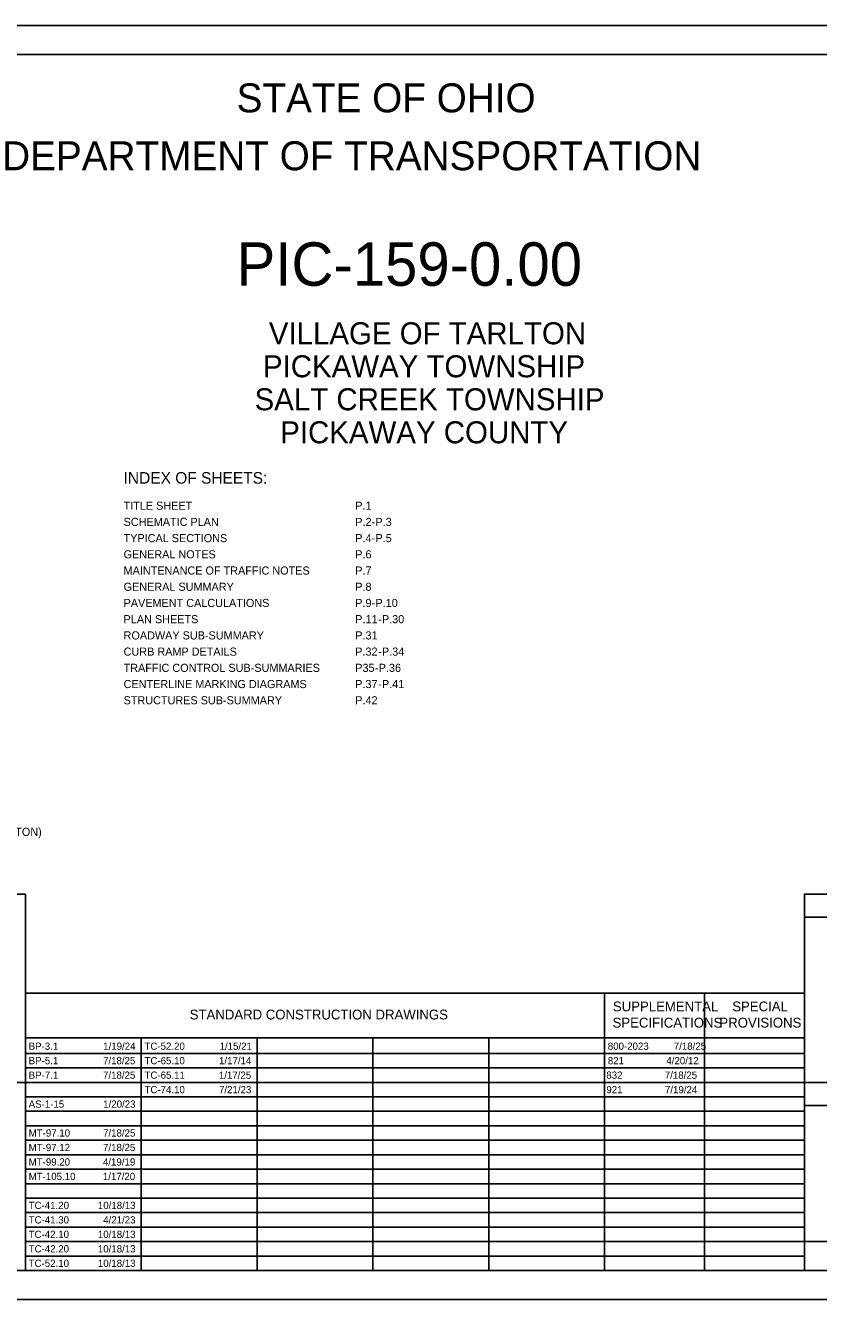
# Model space of a CAD drawing. Extents: x 0 to 42.5, y 0 to 22.
# Drawn here: x 10.15 to 23.84, y 0 to 22 of the extents above; entities that cross this region are included whole.
import ezdxf

# ---------------------------------------------------------------- set-up
doc = ezdxf.new("R2010")
doc.units = 0
for name, color, linetype in [('Default', 7, 'Continuous'), ('SH_Border', 7, 'Continuous'), ('SH_Cut_Line', 7, 'Continuous'), ('SH_Data', 7, 'Continuous'), ('SH_Text', 7, 'Continuous')]:
    doc.layers.add(name, color=color, linetype=linetype)

msp = doc.modelspace()

# ---------------------------------------------------------------- linework, layer by layer
at = {"layer": 'SH_Border'}
msp.add_lwpolyline([(1.5, 21.5), (33.5, 21.5), (33.5, 0.5), (1.5, 0.5)], close=True, dxfattribs=at)
at = {"layer": 'SH_Cut_Line'}
msp.add_lwpolyline([(0, 0), (34, 0), (34, 22), (0, 22)], close=True, dxfattribs=at)
at = {"layer": 'SH_Data'}
for p, q in [((23.6, 6.6), (26.4, 6.6)), ((10.15, 5.292), (23.6, 5.292)), ((10.15, 0.5), (10.15, 5.292)), ((20.15, 0.5), (20.15, 5.292)), ((21.875, 0.5), (21.875, 5.292)), ((23.6, 0.5), (23.6, 5.292)), ((10.15, 4.521), (23.6, 4.521)), ((12.15, 0.5), (12.15, 4.521)), ((14.15, 0.5), (14.15, 4.521)), ((16.15, 0.5), (16.15, 4.521)), ((18.15, 0.5), (18.15, 4.521)), ((10.15, 4.25), (23.6, 4.25)), ((10.15, 4), (23.6, 4)), ((10.15, 3.75), (23.6, 3.75)), ((23.6, 0.5), (23.6, 3.75)), ((23.6, 3.75), (26.4, 3.75)), ((10.15, 3.5), (23.6, 3.5)), ((23.6, 3.35), (26.4, 3.35)), ((23.6, 3.35), (26.4, 3.35)), ((10.15, 3.25), (23.6, 3.25)), ((10.15, 3), (23.6, 3)), ((10.15, 2.75), (23.6, 2.75)), ((10.15, 2.5), (23.6, 2.5)), ((10.15, 2.25), (23.6, 2.25)), ((10.15, 2), (23.6, 2)), ((10.15, 1.75), (23.6, 1.75)), ((10.15, 1.5), (23.6, 1.5)), ((10.15, 1.25), (23.6, 1.25)), ((10.15, 1), (23.6, 1)), ((10.15, 0.75), (23.6, 0.75)), ((23.6, 0.5), (26.4, 0.5))]:
    msp.add_line(p, q, dxfattribs=at)
for points in [[(10.15, 7), (7.35, 7), (7.35, 3.75), (10.15, 3.75)], [(26.4, 7), (23.6, 7), (23.6, 3.75), (26.4, 3.75)], [(10.15, 3.75), (7.35, 3.75), (7.35, 0.5), (10.15, 0.5)], [(26.4, 3.75), (23.6, 3.75), (23.6, 0.5), (26.4, 0.5)], [(23.6, 0.5), (23.6, 1), (26.4, 1), (26.4, 0.5)]]:
    msp.add_lwpolyline(points, close=True, dxfattribs=at)

# ---------------------------------------------------------------- texts
at = {"layer": 'Default'}
for s, p in [('BP-3.1', (10.205, 4.312)), ('1/19/24', (11.492, 4.312)), ('TC-52.20', (12.205, 4.312)), ('1/15/21', (13.502, 4.312)), ('800-2023', (20.205, 4.312)), ('7/18/25', (21.344, 4.312)), ('BP-5.1', (10.205, 4.062)), ('7/18/25', (11.489, 4.062)), ('TC-65.10', (12.205, 4.062)), ('1/17/14', (13.492, 4.062)), ('821', (20.205, 4.062)), ('4/20/12', (21.216, 4.062)), ('BP-7.1', (10.205, 3.812)), ('7/18/25', (11.489, 3.812)), ('TC-65.11', (12.205, 3.812)), ('1/17/25', (13.489, 3.812)), ('832', (20.18, 3.812)), ('7/18/25', (21.189, 3.812)), ('TC-74.10', (12.205, 3.562)), ('7/21/23', (13.492, 3.562)), ('921', (20.18, 3.562)), ('7/19/24', (21.192, 3.562)), ('AS-1-15', (10.205, 3.312)), ('1/20/23', (11.492, 3.312)), ('MT-97.10', (10.205, 2.813)), ('7/18/25', (11.489, 2.813)), ('MT-97.12', (10.205, 2.563)), ('7/18/25', (11.489, 2.563)), ('MT-99.20', (10.205, 2.313)), ('4/19/19', (11.488, 2.313)), ('MT-105.10', (10.205, 2.063)), ('1/17/20', (11.486, 2.063)), ('TC-41.20', (10.205, 1.563)), ('10/18/13', (11.4, 1.563)), ('TC-41.30', (10.205, 1.313)), ('4/21/23', (11.492, 1.313)), ('TC-42.10', (10.205, 1.063)), ('10/18/13', (11.4, 1.063)), ('TC-42.20', (10.205, 0.813)), ('10/18/13', (11.4, 0.813)), ('TC-52.10', (10.205, 0.563)), ('10/18/13', (11.4, 0.563))]:
    msp.add_text(s, height=0.125, dxfattribs=at).set_placement(p)
at = {"layer": 'SH_Text'}
for s, height, p in [('STATE OF OHIO', 0.5, (13.795, 20.5)), ('DEPARTMENT OF TRANSPORTATION', 0.5, (9.747, 19.5)), ('PIC-159-0.00', 0.75, (13.795, 17.505)), ('VILLAGE OF TARLTON', 0.38, (14.352, 16.495)), ('PICKAWAY TOWNSHIP', 0.38, (14.251, 15.925)), ('SALT CREEK TOWNSHIP', 0.38, (14.106, 15.355)), ('PICKAWAY COUNTY', 0.38, (14.549, 14.785)), ('INDEX OF SHEETS:', 0.2, (11.844, 14.088)), ('TITLE SHEET', 0.14, (11.844, 13.638)), ('P.1', 0.14, (15.844, 13.638)), ('SCHEMATIC PLAN', 0.14, (11.844, 13.358)), ('P.2', 0.14, (15.844, 13.358)), ('P.3', 0.14, (16.193, 13.358)), ('TYPICAL SECTIONS', 0.14, (11.844, 13.078)), ('P.4', 0.14, (15.844, 13.078)), ('-', 0.14, (16.126, 13.358)), ('P.5', 0.14, (16.193, 13.078)), ('-', 0.14, (16.126, 13.078)), ('GENERAL NOTES', 0.14, (11.844, 12.798)), ('P.6', 0.14, (15.844, 12.798)), ('MAINTENANCE OF TRAFFIC NOTES', 0.14, (11.844, 12.518)), ('P.7', 0.14, (15.844, 12.518)), ('GENERAL SUMMARY', 0.14, (11.844, 12.238)), ('P.8', 0.14, (15.844, 12.238)), ('PAVEMENT CALCULATIONS', 0.14, (11.844, 11.958)), ('P.9', 0.14, (15.844, 11.958)), ('-', 0.14, (16.126, 11.958)), ('P.10', 0.14, (16.193, 11.958)), ('PLAN SHEETS', 0.14, (11.844, 11.678)), ('P.11', 0.14, (15.844, 11.678)), ('-', 0.14, (16.238, 11.678)), ('P.30', 0.14, (16.305, 11.678)), ('ROADWAY SUB-SUMMARY', 0.14, (11.844, 11.398)), ('P.31', 0.14, (15.844, 11.398)), ('CURB RAMP DETAILS', 0.14, (11.844, 11.118)), ('P.32', 0.14, (15.844, 11.118)), ('P.34', 0.14, (16.305, 11.118)), ('-', 0.14, (16.238, 11.118)), ('TRAFFIC CONTROL SUB-SUMMARIES', 0.14, (11.844, 10.838)), ('P35', 0.14, (15.844, 10.838)), ('-', 0.14, (16.182, 10.838)), ('P.36', 0.14, (16.249, 10.838)), ('CENTERLINE MARKING DIAGRAMS', 0.14, (11.844, 10.558)), ('P.37', 0.14, (15.844, 10.558)), ('-', 0.14, (16.238, 10.558)), ('P.41', 0.14, (16.305, 10.558)), ('STRUCTURES SUB-SUMMARY', 0.14, (11.844, 10.278)), ('P.42', 0.14, (15.844, 10.278)), ('55 MPH (35 MPH IN TARLTON)', 0.14, (7.737, 8.006)), ('SUPPLEMENTAL', 0.17, (20.293, 4.976)), ('SPECIAL', 0.17, (22.354, 4.976)), ('STANDARD CONSTRUCTION DRAWINGS', 0.17, (12.986, 4.836)), ('SPECIFICATIONS', 0.17, (20.287, 4.696)), ('PROVISIONS', 0.17, (22.132, 4.696))]:
    msp.add_text(s, height=height, dxfattribs=at).set_placement(p)

doc.saveas('drawing.dxf')
